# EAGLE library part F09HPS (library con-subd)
SUB-D
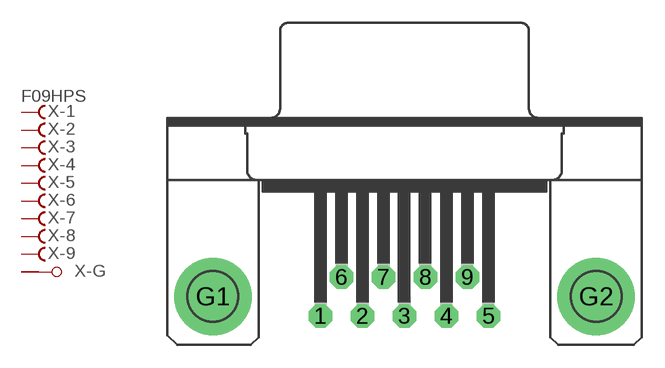
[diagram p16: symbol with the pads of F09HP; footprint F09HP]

Designator prefix X; gates -2=F -3=F -4=F -5=F -6=F -7=F -8=F -9=F -G=GND -1=FV

## F09HPS (OC_FARNELL: unknown; OC_NEWARK: unknown)  [F09HP]
1  -1:F  pas
2  -2:F  pas
3  -3:F  pas
4  -4:F  pas
5  -5:F  pas
6  -6:F  pas
7  -7:F  pas
8  -8:F  pas
9  -9:F  pas
G1  -G:G1  pas
G2  -G:G2  pas

## Footprint F09HP (pad centres in mm)
SUB-D
drill 1.016 octagon: 1 -5.486,-1.27; 2 -2.743,-1.27; 3 0,-1.27; 4 2.743,-1.27; 5 5.486,-1.27; 6 -4.115,1.27; 7 -1.372,1.27; 8 1.372,1.27; 9 4.115,1.27
drill 3.302 pad 5.08 round: G1 -12.522,0; G2 12.522,0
